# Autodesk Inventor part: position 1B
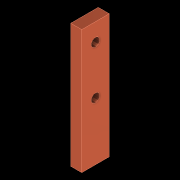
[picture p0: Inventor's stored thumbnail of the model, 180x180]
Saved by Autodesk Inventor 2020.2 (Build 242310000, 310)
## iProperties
Category: 1
Manager: PART
Company: 26
Created: 2020-10
Part Number: position 1B
Material: Generic
Document SubType Name: Modeling
Designer: Apardo
Density: 1 g/cm^3
Appearance: Metal 1400F Hot
Vendor: 1B
Project: PLATE ROLLING MACHINE
Cost Center: 1
Engineer: STEEL C45
Stock Number: 3.2
Engr Approved By: D. JAEGER
Author: Apardo
Revision Number: 1.0
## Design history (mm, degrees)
sketch "Sketch1"
  geometry: L1 (4, 10)-(-4, 10); L2 (-4, 10)-(-4, -10); L3 (-4, -10)-(4, -10); L4 (4, -10)-(4, 10); L5 (4, 10)-(-4, -10); L6 (-4, 10)-(4, -10); 1 further point
  constraints: 12 end point, 2 midpoint, 2 parallel, 1 horizontal, 1 perpendicular
  dimensions: "d0" = 20 distance of L3.end L1.start; "d1" = 8 distance of L2.end L3.end
extrude "Extrusion1" new body sketch "Sketch1" stored distance "d2" = 90; taper "d3" = 0 deg
sketch "Sketch2"
  geometry: L1 (0, 0)-(-20, 0) reference; 3 further points
  constraints: 2 vertical alignment
  dimensions: "d4" = 35 distance of point (-10, 77) point (-10, 42); "d5" = 42 distance from line of L1 point (-10, 42)
hole "Hole1" sketch "Sketch2" at (-10, 42), (-10, 77) diameter "d6" = 6.2; stored, may be unused: countersink angle "d10" = 90 deg, drill point angle "d12" = 118 deg; dims "d7" = 16, "d8" = 12, "d9" = 2, "d11" = 8
body "Solid1"
